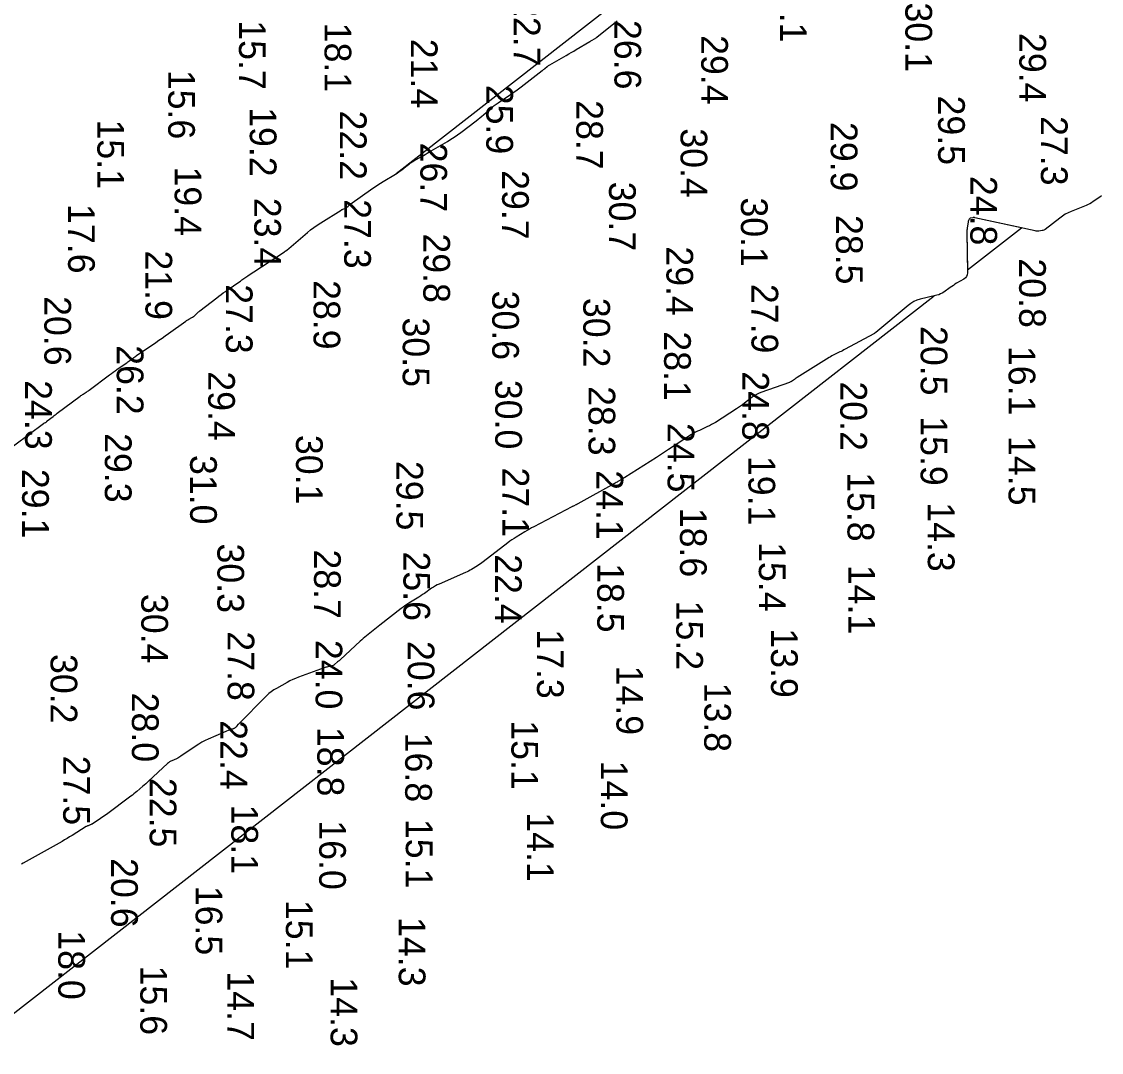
# Model space of a CAD drawing. Extents: x 1178573 to 1187098, y 693282 to 751751.
# Drawn here: x 1180549 to 1181054, y 720505 to 720988 of the extents above; entities that cross this region are included whole.
import ezdxf

# ---------------------------------------------------------------- set-up
doc = ezdxf.new("R2010")
doc.units = 0
for name, color, linetype in [('G-ANNO-PATT', 7, 'Continuous'), ('V-HYDS-MAJR', 7, 'Continuous'), ('V-HYDS-SOUN', 7, 'Continuous')]:
    doc.layers.add(name, color=color, linetype=linetype)

msp = doc.modelspace()

# ---------------------------------------------------------------- linework, layer by layer
at = {"layer": 'G-ANNO-PATT'}
msp.add_line((1180991.61, 720871.33), (1181016.89, 720891.03), dxfattribs=at)
for points in [[(1182192.54, 723969.84), (1182074.29, 722609.41), (1181796.18, 721896.63), (1181517.07, 721534.37), (1180724.06, 720916.39)], [(1180724.06, 720916.39), (1180724.56, 720916.71), (1180725.29, 720917.19), (1180726, 720917.7), (1180726.69, 720918.23), (1180729.44, 720920.39), (1180730.14, 720920.92), (1180730.85, 720921.42), (1180731.58, 720921.89), (1180732.33, 720922.34), (1180735.98, 720924.44), (1180736.85, 720924.93), (1180737.71, 720925.43), (1180738.56, 720925.93), (1180739.42, 720926.43), (1180748.12, 720931.52), (1180749.73, 720932.5), (1180751.31, 720933.52), (1180752.85, 720934.59), (1180754.37, 720935.7), (1180761.6, 720941.2), (1180762.48, 720941.88), (1180763.34, 720942.56), (1180764.19, 720943.27), (1180765.03, 720943.98), (1180768.36, 720946.88), (1180769.2, 720947.59), (1180770.06, 720948.27), (1180770.95, 720948.93), (1180771.85, 720949.56), (1180777.64, 720953.47), (1180778.9, 720954.33), (1180780.15, 720955.22), (1180781.39, 720956.12), (1180782.61, 720957.04), (1180792.53, 720964.64), (1180792.82, 720964.87), (1180793.12, 720965.1), (1180793.41, 720965.34), (1180793.7, 720965.57), (1180794.86, 720966.53), (1180795.16, 720966.77), (1180795.46, 720966.99), (1180795.77, 720967.19), (1180796.09, 720967.39), (1180803.76, 720971.8), (1180804.92, 720972.47), (1180806.08, 720973.14), (1180807.24, 720973.82), (1180808.4, 720974.5), (1180814.78, 720978.26), (1180815.06, 720978.42), (1180815.33, 720978.58), (1180815.6, 720978.74), (1180815.88, 720978.9), (1180816.97, 720979.55), (1180817.24, 720979.72), (1180817.5, 720979.89), (1180817.76, 720980.08), (1180818.01, 720980.27), (1180827.6, 720987.94)], [(1181016.89, 720891.03), (1180995.09, 720895.78), (1180994.85, 720895.82), (1180994.61, 720895.84), (1180994.37, 720895.83), (1180994.13, 720895.79), (1180993.06, 720895.56), (1180992.88, 720895.51), (1180992.73, 720895.42), (1180992.6, 720895.29), (1180992.49, 720895.14), (1180992.12, 720894.46), (1180992.03, 720894.29), (1180991.97, 720894.11), (1180991.91, 720893.92), (1180991.88, 720893.73), (1180991.5, 720891), (1180991.44, 720890.48), (1180991.4, 720889.96), (1180991.38, 720889.43), (1180991.38, 720888.91), (1180991.61, 720871.33)], [(1179618.07, 719554.17), (1179993.05, 720093.17), (1180976.01, 720859.17)], [(1180976.01, 720859.17), (1180969.53, 720857.59), (1180967.98, 720857.12), (1180966.52, 720856.49), (1180965.14, 720855.69), (1180963.84, 720854.73), (1180948.65, 720842.1), (1180948.61, 720842.07), (1180948.57, 720842.04), (1180948.54, 720842.01), (1180948.5, 720841.99), (1180948.34, 720841.88), (1180948.31, 720841.85), (1180948.27, 720841.82), (1180948.23, 720841.79), (1180948.2, 720841.76), (1180948, 720841.56), (1180947.96, 720841.52), (1180947.91, 720841.48), (1180947.86, 720841.44), (1180947.8, 720841.41), (1180934.39, 720834.19), (1180933.76, 720833.86), (1180933.14, 720833.53), (1180932.5, 720833.22), (1180931.87, 720832.91), (1180929.32, 720831.7), (1180928.68, 720831.39), (1180928.06, 720831.06), (1180927.44, 720830.71), (1180926.84, 720830.35), (1180911.82, 720821.02), (1180911.68, 720820.92), (1180911.54, 720820.83), (1180911.4, 720820.72), (1180911.26, 720820.62), (1180910.73, 720820.18), (1180910.59, 720820.07), (1180910.45, 720819.97), (1180910.31, 720819.87), (1180910.17, 720819.77), (1180909.16, 720819.13), (1180908.94, 720818.99), (1180908.71, 720818.87), (1180908.48, 720818.77), (1180908.24, 720818.68), (1180894.87, 720813.94), (1180893.8, 720813.52), (1180892.78, 720813.01), (1180891.8, 720812.42), (1180890.86, 720811.75), (1180887.21, 720808.91), (1180886.29, 720808.21), (1180885.36, 720807.53), (1180884.4, 720806.88), (1180883.44, 720806.24), (1180873.56, 720799.94), (1180872.67, 720799.4), (1180871.77, 720798.89), (1180870.85, 720798.41), (1180869.91, 720797.96), (1180866.12, 720796.23), (1180865.18, 720795.78), (1180864.26, 720795.3), (1180863.35, 720794.78), (1180862.47, 720794.24), (1180851.66, 720787.31), (1180851.19, 720787.01), (1180850.71, 720786.7), (1180850.24, 720786.38), (1180849.78, 720786.06), (1180847.91, 720784.78), (1180847.45, 720784.46), (1180846.98, 720784.14), (1180846.5, 720783.84), (1180846.03, 720783.53), (1180831.21, 720774.2), (1180830.8, 720773.95), (1180830.39, 720773.7), (1180829.98, 720773.45), (1180829.57, 720773.2), (1180827.92, 720772.23), (1180827.51, 720771.98), (1180827.09, 720771.74), (1180826.68, 720771.51), (1180826.26, 720771.27), (1180809.19, 720761.79), (1180809.1, 720761.75), (1180809.02, 720761.7), (1180808.94, 720761.66), (1180808.85, 720761.62), (1180808.51, 720761.46), (1180808.43, 720761.42), (1180808.34, 720761.38), (1180808.26, 720761.34), (1180808.17, 720761.3), (1180807.13, 720760.8), (1180806.93, 720760.71), (1180806.72, 720760.61), (1180806.52, 720760.5), (1180806.33, 720760.4), (1180788.55, 720751.08), (1180787.5, 720750.52), (1180786.46, 720749.94), (1180785.43, 720749.35), (1180784.4, 720748.74), (1180780.32, 720746.29), (1180779.32, 720745.66), (1180778.33, 720745), (1180777.36, 720744.31), (1180776.41, 720743.6), (1180764.82, 720734.6), (1180764.18, 720734.12), (1180763.52, 720733.66), (1180762.86, 720733.21), (1180762.17, 720732.79), (1180759.42, 720731.12), (1180758.73, 720730.72), (1180758.02, 720730.34), (1180757.3, 720729.98), (1180756.57, 720729.65), (1180744.29, 720724.28), (1180743.36, 720723.85), (1180742.45, 720723.37), (1180741.57, 720722.84), (1180740.71, 720722.27), (1180737.33, 720719.91), (1180736.48, 720719.32), (1180735.62, 720718.75), (1180734.76, 720718.18), (1180733.88, 720717.63), (1180730.04, 720715.24), (1180729.12, 720714.65), (1180728.21, 720714.04), (1180727.32, 720713.4), (1180726.45, 720712.74), (1180716.45, 720704.97), (1180715.67, 720704.36), (1180714.89, 720703.75), (1180714.11, 720703.13), (1180713.33, 720702.51), (1180710.24, 720700.04), (1180709.47, 720699.41), (1180708.71, 720698.77), (1180707.96, 720698.12), (1180707.23, 720697.45), (1180698.03, 720688.99), (1180697.7, 720688.69), (1180697.36, 720688.38), (1180697.02, 720688.08), (1180696.68, 720687.78), (1180695.29, 720686.55), (1180694.95, 720686.29), (1180694.58, 720686.08), (1180694.19, 720685.92), (1180693.78, 720685.81), (1180692.07, 720685.48), (1180691.64, 720685.39), (1180691.22, 720685.28), (1180690.81, 720685.15), (1180690.4, 720685.01), (1180678.35, 720680.61), (1180677, 720680.09), (1180675.67, 720679.51), (1180674.36, 720678.89), (1180673.08, 720678.22), (1180667.99, 720675.42), (1180666.75, 720674.68), (1180665.58, 720673.86), (1180664.46, 720672.96), (1180663.41, 720671.97), (1180650.12, 720658.58), (1180649.99, 720658.45), (1180649.86, 720658.31), (1180649.74, 720658.16), (1180649.62, 720658.02), (1180649.12, 720657.35), (1180649.02, 720657.24), (1180648.92, 720657.13), (1180648.81, 720657.03), (1180648.69, 720656.94), (1180648.15, 720656.57), (1180648.05, 720656.51), (1180647.95, 720656.46), (1180647.84, 720656.43), (1180647.72, 720656.41), (1180647.25, 720656.36), (1180647.14, 720656.35), (1180647.02, 720656.32), (1180646.91, 720656.29), (1180646.8, 720656.25), (1180636.05, 720651.62), (1180634.58, 720650.94), (1180633.14, 720650.19), (1180631.74, 720649.37), (1180630.38, 720648.49), (1180623.33, 720643.62), (1180622.83, 720643.3), (1180622.32, 720643), (1180621.79, 720642.72), (1180621.25, 720642.47), (1180619.06, 720641.52), (1180618.52, 720641.26), (1180618.01, 720640.96), (1180617.53, 720640.62), (1180617.08, 720640.24), (1180608.15, 720631.99), (1180607.48, 720631.38), (1180606.81, 720630.77), (1180606.13, 720630.17), (1180605.45, 720629.58), (1180602.71, 720627.21), (1180602.02, 720626.63), (1180601.32, 720626.05), (1180600.61, 720625.49), (1180599.89, 720624.94), (1180588.42, 720616.37), (1180587.73, 720615.86), (1180587.03, 720615.37), (1180586.32, 720614.89), (1180585.6, 720614.42), (1180581.67, 720611.91), (1180581.45, 720611.78), (1180581.23, 720611.67), (1180581, 720611.56), (1180580.77, 720611.47), (1180579.81, 720611.12), (1180579.57, 720611.03), (1180579.34, 720610.92), (1180579.12, 720610.81), (1180578.9, 720610.68), (1180572.36, 720606.58), (1180571.19, 720605.86), (1180570.02, 720605.16), (1180568.83, 720604.47), (1180567.64, 720603.79), (1180549.43, 720593.6), (1180548.61, 720593.13)]]:
    msp.add_lwpolyline(points, dxfattribs=at)
at = {"layer": 'V-HYDS-MAJR'}
for points in [[(1180538.84, 720784.48), (1180559.02, 720799.49), (1180559.12, 720799.56), (1180559.22, 720799.62), (1180559.32, 720799.67), (1180559.43, 720799.72), (1180559.92, 720799.9), (1180560, 720799.93), (1180560.08, 720799.98), (1180560.15, 720800.04), (1180560.21, 720800.11), (1180560.44, 720800.42), (1180560.5, 720800.49), (1180560.56, 720800.56), (1180560.63, 720800.63), (1180560.7, 720800.69), (1180563.43, 720802.76), (1180563.91, 720803.12), (1180564.39, 720803.48), (1180564.87, 720803.84), (1180565.36, 720804.2), (1180576.17, 720812.23), (1180576.5, 720812.47), (1180576.84, 720812.71), (1180577.18, 720812.94), (1180577.53, 720813.16), (1180578.92, 720814.04), (1180579.27, 720814.26), (1180579.61, 720814.5), (1180579.95, 720814.73), (1180580.28, 720814.98), (1180589.91, 720822.18), (1180590.76, 720822.81), (1180591.61, 720823.44), (1180592.47, 720824.06), (1180593.33, 720824.67), (1180597.71, 720827.74), (1180598.11, 720828.03), (1180598.51, 720828.32), (1180598.92, 720828.61), (1180599.32, 720828.9), (1180600.91, 720830.09), (1180601.31, 720830.38), (1180601.72, 720830.67), (1180602.12, 720830.96), (1180602.53, 720831.24), (1180611.49, 720837.37), (1180612.98, 720838.4), (1180614.46, 720839.43), (1180615.94, 720840.47), (1180617.41, 720841.52), (1180625.56, 720847.35), (1180625.9, 720847.59), (1180626.25, 720847.82), (1180626.61, 720848.03), (1180626.97, 720848.24), (1180628.45, 720849.04), (1180628.8, 720849.25), (1180629.14, 720849.47), (1180629.45, 720849.72), (1180629.76, 720849.99), (1180630.93, 720851.12), (1180631.22, 720851.4), (1180631.53, 720851.67), (1180631.84, 720851.93), (1180632.16, 720852.18), (1180640.05, 720858.28), (1180641.06, 720859.05), (1180642.09, 720859.81), (1180643.12, 720860.56), (1180644.16, 720861.3), (1180649.06, 720864.7), (1180649.75, 720865.19), (1180650.44, 720865.67), (1180651.13, 720866.15), (1180651.83, 720866.63), (1180654.6, 720868.56), (1180655.29, 720869.04), (1180655.99, 720869.51), (1180656.69, 720869.98), (1180657.4, 720870.45), (1180671.81, 720879.86), (1180671.95, 720879.96), (1180672.09, 720880.05), (1180672.23, 720880.15), (1180672.37, 720880.24), (1180673.04, 720880.73), (1180673.12, 720880.78), (1180673.19, 720880.84), (1180673.26, 720880.89), (1180673.34, 720880.94), (1180673.63, 720881.15), (1180673.7, 720881.2), (1180673.77, 720881.26), (1180673.84, 720881.31), (1180673.91, 720881.37), (1180682.57, 720888.85), (1180684.06, 720890.08), (1180685.59, 720891.26), (1180687.17, 720892.37), (1180688.8, 720893.42), (1180698.33, 720899.33), (1180698.53, 720899.45), (1180698.73, 720899.56), (1180698.94, 720899.65), (1180699.16, 720899.74), (1180700.03, 720900.06), (1180700.24, 720900.15), (1180700.44, 720900.26), (1180700.63, 720900.39), (1180700.81, 720900.53), (1180701.64, 720901.25), (1180701.83, 720901.42), (1180702.04, 720901.59), (1180702.24, 720901.74), (1180702.45, 720901.9), (1180713.23, 720909.54), (1180714.41, 720910.36), (1180715.59, 720911.15), (1180716.79, 720911.93), (1180718, 720912.68), (1180723.82, 720916.24), (1180724.56, 720916.71), (1180725.29, 720917.19), (1180726, 720917.7), (1180726.69, 720918.23), (1180729.44, 720920.39), (1180730.14, 720920.92), (1180730.85, 720921.42), (1180731.58, 720921.89), (1180732.33, 720922.34), (1180735.98, 720924.44), (1180736.85, 720924.93), (1180737.71, 720925.43), (1180738.56, 720925.93), (1180739.42, 720926.43), (1180748.12, 720931.52), (1180749.73, 720932.5), (1180751.31, 720933.52), (1180752.85, 720934.59), (1180754.37, 720935.7), (1180761.6, 720941.2), (1180762.48, 720941.88), (1180763.34, 720942.56), (1180764.19, 720943.27), (1180765.03, 720943.98), (1180768.36, 720946.88), (1180769.2, 720947.59), (1180770.06, 720948.27), (1180770.95, 720948.93), (1180771.85, 720949.56), (1180777.64, 720953.47), (1180778.9, 720954.33), (1180780.15, 720955.22), (1180781.39, 720956.12), (1180782.61, 720957.04), (1180792.53, 720964.64), (1180792.82, 720964.87), (1180793.12, 720965.1), (1180793.41, 720965.34), (1180793.7, 720965.57), (1180794.86, 720966.53), (1180795.16, 720966.77), (1180795.46, 720966.99), (1180795.77, 720967.19), (1180796.09, 720967.39), (1180803.76, 720971.8), (1180804.92, 720972.47), (1180806.08, 720973.14), (1180807.24, 720973.82), (1180808.4, 720974.5), (1180814.78, 720978.26), (1180815.06, 720978.42), (1180815.33, 720978.58), (1180815.6, 720978.74), (1180815.88, 720978.9), (1180816.97, 720979.55), (1180817.24, 720979.72), (1180817.5, 720979.89), (1180817.76, 720980.08), (1180818.01, 720980.27), (1180827.6, 720987.94)], [(1181054.36, 720905.96), (1181053.58, 720905.44), (1181050.53, 720903.32), (1181049.75, 720902.81), (1181048.95, 720902.35), (1181048.12, 720901.94), (1181047.27, 720901.57), (1181040.22, 720898.75), (1181038.78, 720898.12), (1181037.41, 720897.39), (1181036.09, 720896.57), (1181034.82, 720895.64), (1181028.04, 720890.33), (1181027.71, 720890.1), (1181027.36, 720889.93), (1181026.99, 720889.8), (1181026.59, 720889.73), (1181024.97, 720889.54), (1181024.57, 720889.51), (1181024.17, 720889.51), (1181023.77, 720889.54), (1181023.37, 720889.61), (1180995.09, 720895.78), (1180994.85, 720895.82), (1180994.61, 720895.84), (1180994.37, 720895.83), (1180994.13, 720895.79), (1180993.06, 720895.56), (1180992.88, 720895.51), (1180992.73, 720895.42), (1180992.6, 720895.29), (1180992.49, 720895.14), (1180992.12, 720894.46), (1180992.03, 720894.29), (1180991.97, 720894.11), (1180991.91, 720893.92), (1180991.88, 720893.73), (1180991.5, 720891), (1180991.44, 720890.48), (1180991.4, 720889.96), (1180991.38, 720889.43), (1180991.38, 720888.91), (1180991.63, 720869.96), (1180991.53, 720869.06), (1180991.23, 720868.27), (1180990.71, 720867.61), (1180989.99, 720867.06), (1180986.56, 720865.07), (1180985.78, 720864.6), (1180985.01, 720864.11), (1180984.25, 720863.61), (1180983.5, 720863.09), (1180980.53, 720860.97), (1180979.77, 720860.48), (1180978.98, 720860.07), (1180978.15, 720859.73), (1180977.28, 720859.48), (1180969.53, 720857.59), (1180967.98, 720857.12), (1180966.52, 720856.49), (1180965.14, 720855.69), (1180963.84, 720854.73), (1180948.65, 720842.1), (1180948.61, 720842.07), (1180948.57, 720842.04), (1180948.54, 720842.01), (1180948.5, 720841.99), (1180948.34, 720841.88), (1180948.31, 720841.85), (1180948.27, 720841.82), (1180948.23, 720841.79), (1180948.2, 720841.76), (1180948, 720841.56), (1180947.96, 720841.52), (1180947.91, 720841.48), (1180947.86, 720841.44), (1180947.8, 720841.41), (1180934.39, 720834.19), (1180933.76, 720833.86), (1180933.14, 720833.53), (1180932.5, 720833.22), (1180931.87, 720832.91), (1180929.32, 720831.7), (1180928.68, 720831.39), (1180928.06, 720831.06), (1180927.44, 720830.71), (1180926.84, 720830.35), (1180911.82, 720821.02), (1180911.68, 720820.92), (1180911.54, 720820.83), (1180911.4, 720820.72), (1180911.26, 720820.62), (1180910.73, 720820.18), (1180910.59, 720820.07), (1180910.45, 720819.97), (1180910.31, 720819.87), (1180910.17, 720819.77), (1180909.16, 720819.13), (1180908.94, 720818.99), (1180908.71, 720818.87), (1180908.48, 720818.77), (1180908.24, 720818.68), (1180894.87, 720813.94), (1180893.8, 720813.52), (1180892.78, 720813.01), (1180891.8, 720812.42), (1180890.86, 720811.75), (1180887.21, 720808.91), (1180886.29, 720808.21), (1180885.36, 720807.53), (1180884.4, 720806.88), (1180883.44, 720806.24), (1180873.56, 720799.94), (1180872.67, 720799.4), (1180871.77, 720798.89), (1180870.85, 720798.41), (1180869.91, 720797.96), (1180866.12, 720796.23), (1180865.18, 720795.78), (1180864.26, 720795.3), (1180863.35, 720794.78), (1180862.47, 720794.24), (1180851.66, 720787.31), (1180851.19, 720787.01), (1180850.71, 720786.7), (1180850.24, 720786.38), (1180849.78, 720786.06), (1180847.91, 720784.78), (1180847.45, 720784.46), (1180846.98, 720784.14), (1180846.5, 720783.84), (1180846.03, 720783.53), (1180831.21, 720774.2), (1180830.8, 720773.95), (1180830.39, 720773.7), (1180829.98, 720773.45), (1180829.57, 720773.2), (1180827.92, 720772.23), (1180827.51, 720771.98), (1180827.09, 720771.74), (1180826.68, 720771.51), (1180826.26, 720771.27), (1180809.19, 720761.79), (1180809.1, 720761.75), (1180809.02, 720761.7), (1180808.94, 720761.66), (1180808.85, 720761.62), (1180808.51, 720761.46), (1180808.43, 720761.42), (1180808.34, 720761.38), (1180808.26, 720761.34), (1180808.17, 720761.3), (1180807.13, 720760.8), (1180806.93, 720760.71), (1180806.72, 720760.61), (1180806.52, 720760.5), (1180806.33, 720760.4), (1180788.55, 720751.08), (1180787.5, 720750.52), (1180786.46, 720749.94), (1180785.43, 720749.35), (1180784.4, 720748.74), (1180780.32, 720746.29), (1180779.32, 720745.66), (1180778.33, 720745), (1180777.36, 720744.31), (1180776.41, 720743.6), (1180764.82, 720734.6), (1180764.18, 720734.12), (1180763.52, 720733.66), (1180762.86, 720733.21), (1180762.17, 720732.79), (1180759.42, 720731.12), (1180758.73, 720730.72), (1180758.02, 720730.34), (1180757.3, 720729.98), (1180756.57, 720729.65), (1180744.29, 720724.28), (1180743.36, 720723.85), (1180742.45, 720723.37), (1180741.57, 720722.84), (1180740.71, 720722.27), (1180737.33, 720719.91), (1180736.48, 720719.32), (1180735.62, 720718.75), (1180734.76, 720718.18), (1180733.88, 720717.63), (1180730.04, 720715.24), (1180729.12, 720714.65), (1180728.21, 720714.04), (1180727.32, 720713.4), (1180726.45, 720712.74), (1180716.45, 720704.97), (1180715.67, 720704.36), (1180714.89, 720703.75), (1180714.11, 720703.13), (1180713.33, 720702.51), (1180710.24, 720700.04), (1180709.47, 720699.41), (1180708.71, 720698.77), (1180707.96, 720698.12), (1180707.23, 720697.45), (1180698.03, 720688.99), (1180697.7, 720688.69), (1180697.36, 720688.38), (1180697.02, 720688.08), (1180696.68, 720687.78), (1180695.29, 720686.55), (1180694.95, 720686.29), (1180694.58, 720686.08), (1180694.19, 720685.92), (1180693.78, 720685.81), (1180692.07, 720685.48), (1180691.64, 720685.39), (1180691.22, 720685.28), (1180690.81, 720685.15), (1180690.4, 720685.01), (1180678.35, 720680.61), (1180677, 720680.09), (1180675.67, 720679.51), (1180674.36, 720678.89), (1180673.08, 720678.22), (1180667.99, 720675.42), (1180666.75, 720674.68), (1180665.58, 720673.86), (1180664.46, 720672.96), (1180663.41, 720671.97), (1180650.12, 720658.58), (1180649.99, 720658.45), (1180649.86, 720658.31), (1180649.74, 720658.16), (1180649.62, 720658.02), (1180649.12, 720657.35), (1180649.02, 720657.24), (1180648.92, 720657.13), (1180648.81, 720657.03), (1180648.69, 720656.94), (1180648.15, 720656.57), (1180648.05, 720656.51), (1180647.95, 720656.46), (1180647.84, 720656.43), (1180647.72, 720656.41), (1180647.25, 720656.36), (1180647.14, 720656.35), (1180647.02, 720656.32), (1180646.91, 720656.29), (1180646.8, 720656.25), (1180636.05, 720651.62), (1180634.58, 720650.94), (1180633.14, 720650.19), (1180631.74, 720649.37), (1180630.38, 720648.49), (1180623.33, 720643.62), (1180622.83, 720643.3), (1180622.32, 720643), (1180621.79, 720642.72), (1180621.25, 720642.47), (1180619.06, 720641.52), (1180618.52, 720641.26), (1180618.01, 720640.96), (1180617.53, 720640.62), (1180617.08, 720640.24), (1180608.15, 720631.99), (1180607.48, 720631.38), (1180606.81, 720630.77), (1180606.13, 720630.17), (1180605.45, 720629.58), (1180602.71, 720627.21), (1180602.02, 720626.63), (1180601.32, 720626.05), (1180600.61, 720625.49), (1180599.89, 720624.94), (1180588.42, 720616.37), (1180587.73, 720615.86), (1180587.03, 720615.37), (1180586.32, 720614.89), (1180585.6, 720614.42), (1180581.67, 720611.91), (1180581.45, 720611.78), (1180581.23, 720611.67), (1180581, 720611.56), (1180580.77, 720611.47), (1180579.81, 720611.12), (1180579.57, 720611.03), (1180579.34, 720610.92), (1180579.12, 720610.81), (1180578.9, 720610.68), (1180572.36, 720606.58), (1180571.19, 720605.86), (1180570.02, 720605.16), (1180568.83, 720604.47), (1180567.64, 720603.79), (1180549.43, 720593.6), (1180548.61, 720593.13)]]:
    msp.add_lwpolyline(points, dxfattribs=at)

# ---------------------------------------------------------------- texts
at = {"layer": 'V-HYDS-SOUN'}
for s, p in [('29.1 ', (1180903.85, 721010.41)), ('22.7 ', (1180779.13, 720999.09)), ('30.1 ', (1180962.54, 720996.56)), ('15.7 ', (1180650.49, 720988.23)), ('26.6 ', (1180826.31, 720988.37)), ('18.1 ', (1180690.56, 720987.08)), ('21.4 ', (1180730.97, 720979.58)), ('29.4 ', (1180866.96, 720981.29)), ('29.4 ', (1181015.91, 720982.27)), ('15.6 ', (1180617.35, 720965.04)), ('25.9 ', (1180766.31, 720958.02)), ('29.5 ', (1180977.89, 720952.98)), ('19.2 ', (1180655.56, 720947.55)), ('28.7 ', (1180808.46, 720950.83)), ('22.2 ', (1180697.75, 720945.97)), ('27.3 ', (1181026.01, 720943.38)), ('15.1 ', (1180584.19, 720941.77)), ('30.4 ', (1180857.28, 720937.65)), ('29.9 ', (1180927.6, 720940.6)), ('26.7 ', (1180735.43, 720930.92)), ('19.4 ', (1180620.37, 720919.77)), ('29.7 ', (1180773.72, 720918.06)), ('30.7 ', (1180823.78, 720912.64)), ('24.8 ', (1180992.98, 720915.37)), ('17.6 ', (1180570.47, 720902.18)), ('23.4 ', (1180657.64, 720905.11)), ('27.3 ', (1180699.77, 720904.47)), ('30.1 ', (1180885.54, 720905.29)), ('28.5 ', (1180930.09, 720897.07)), ('29.8 ', (1180736.82, 720888.43)), ('29.4 ', (1180850.65, 720882.37)), ('21.9 ', (1180606.7, 720880.46)), ('20.8 ', (1181015.82, 720876.75)), ('28.9 ', (1180685.41, 720866.58)), ('27.3 ', (1180644.35, 720864.64)), ('30.6 ', (1180769.09, 720861.66)), ('27.9 ', (1180890.49, 720864.81)), ('20.6 ', (1180559.35, 720859.07)), ('30.2 ', (1180811.73, 720858.24)), ('30.5 ', (1180727.17, 720849.07)), ('28.1 ', (1180849.58, 720842.59)), ('20.5 ', (1180969.72, 720845.07)), ('26.2 ', (1180593.26, 720836.1)), ('16.1 ', (1181010.9, 720835.77)), ('29.4 ', (1180636.08, 720823.88)), ('24.8 ', (1180886.19, 720823.87)), ('24.3 ', (1180550.36, 720819.73)), ('30.0 ', (1180770.5, 720819.87)), ('28.3 ', (1180814.17, 720816.94)), ('20.2 ', (1180932.07, 720819.14)), ('15.9 ', (1180969.69, 720802.83)), ('24.5 ', (1180851.19, 720799.7)), ('29.3 ', (1180587.69, 720794.93)), ('30.1 ', (1180677.21, 720794.1)), ('14.5 ', (1181010.86, 720793.56)), ('31.0 ', (1180627.62, 720784.7)), ('29.5 ', (1180724.22, 720781.92)), ('19.1 ', (1180889.08, 720784.26)), ('29.1 ', (1180548.96, 720778.19)), ('27.1 ', (1180773.83, 720778.84)), ('24.1 ', (1180817.89, 720777.56)), ('15.8 ', (1180935.44, 720776.65)), ('14.3 ', (1180973.06, 720762.58)), ('18.6 ', (1180857.02, 720759.99)), ('30.3 ', (1180640.38, 720743.25)), ('28.7 ', (1180685.66, 720740.46)), ('15.4 ', (1180893.93, 720743.92)), ('25.6 ', (1180727.49, 720739.51)), ('22.4 ', (1180770.37, 720738.24)), ('18.5 ', (1180818.28, 720734.08)), ('14.1 ', (1180935.9, 720733.27)), ('30.4 ', (1180604.75, 720719.64)), ('15.2 ', (1180855.27, 720716.48)), ('27.8 ', (1180645.15, 720702.14)), ('17.3 ', (1180790.05, 720703.1)), ('13.9 ', (1180899.64, 720703.52)), ('24.0 ', (1180686.38, 720698.12)), ('20.6 ', (1180729.52, 720697.62)), ('30.2 ', (1180562.26, 720691.51)), ('14.9 ', (1180827.24, 720686.1)), ('13.8 ', (1180868.35, 720678.13)), ('28.0 ', (1180600.36, 720673.41)), ('22.4 ', (1180641.83, 720660.52)), ('15.1 ', (1180778.06, 720660.5)), ('18.8 ', (1180687.18, 720657.39)), ('16.8 ', (1180728.32, 720654.67)), ('27.5 ', (1180568.18, 720643.92)), ('14.0 ', (1180819.94, 720641.56)), ('22.5 ', (1180608.7, 720633.52)), ('18.1 ', (1180646.92, 720621)), ('15.1 ', (1180728.62, 720614.31)), ('14.1 ', (1180785.41, 720617.39)), ('16.0 ', (1180688.05, 720613.64)), ('20.6 ', (1180590.61, 720595.95)), ('16.5 ', (1180630.19, 720583)), ('15.1 ', (1180672.45, 720576.38)), ('14.3 ', (1180725.32, 720568.35)), ('18.0 ', (1180565.88, 720562.16)), ('15.6 ', (1180604.29, 720545.62)), ('14.7 ', (1180645.07, 720542.89)), ('14.3 ', (1180693.43, 720540.11))]:
    msp.add_text(s, height=12.5, rotation=270, dxfattribs=at).set_placement(p)

doc.saveas('drawing.dxf')
